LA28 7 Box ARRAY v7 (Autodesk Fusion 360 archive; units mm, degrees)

design "LA28 7 Box ARRAY" references "LA28 TOUR BLOCK", "LA28 RF1 Sheet Metal Assembly"
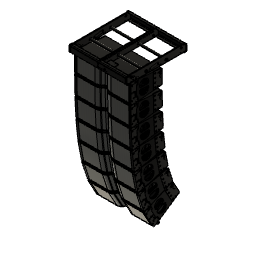
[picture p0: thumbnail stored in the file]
component_insert "Component Insert1"
as_built_joint "As-built1"
component_insert "Component Insert2"
joint "Assemble1" alignAngle 0 alignOffsetX 0 alignOffsetY 0 alignOffsetZ 5.08
component_insert "Component Insert3"
joint "Assemble2" alignAngle -1 alignOffsetX 0 alignOffsetY 0 alignOffsetZ 5.08
component_insert "Component Insert4"
component_insert "Component Insert5"
joint "Assemble3" alignAngle -2 alignOffsetX 0 alignOffsetY 0 alignOffsetZ 5.08
joint "Assemble4" alignAngle -3 alignOffsetX 0 alignOffsetY 0 alignOffsetZ 5.08
component_insert "Component Insert6"
component_insert "Component Insert7"
component_insert "Component Insert8"
joint "Assemble5" alignAngle -5 alignOffsetX 0 alignOffsetY 0 alignOffsetZ 5.08
joint "Assemble6" alignAngle -7 alignOffsetX 0 alignOffsetY 0 alignOffsetZ 5.08
joint "Assemble7" alignAngle -11 alignOffsetX 0 alignOffsetY 0 alignOffsetZ 5.08

design "la28RF1 SHEET METAL ASSEMBLY.SLDASM"
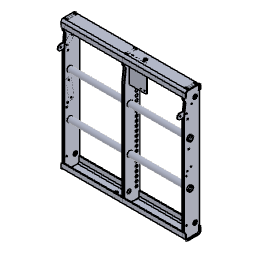
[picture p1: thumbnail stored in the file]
named bodies: "Cut-Extrude3", "Cut-Extrude2", "Mirror2", "Boss-Extrude1"

design "LA28 TOUR BLOCK" references "LA28 TOUR BLOCK.sldprt"
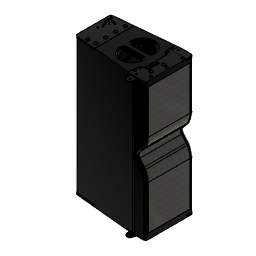
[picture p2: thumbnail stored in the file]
step "WorkingModel"
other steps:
derived_base_feature "Derived Base Feature" bodies "Fillet3"
named bodies: "Fillet3"

design "LA28 RF1 Sheet Metal Assembly" references "la28RF1 SHEET METAL ASSEMBLY.SLDASM"
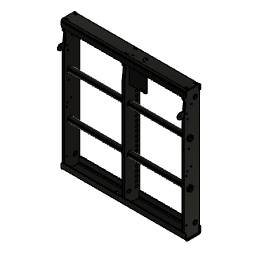
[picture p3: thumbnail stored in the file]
step "WorkingModel"
derived_instance "DerivedInstance1"
derived_instance "DerivedInstance2"
derived_instance "DerivedInstance3"
derived_instance "DerivedInstance4"
derived_instance "DerivedInstance5"
derived_instance "DerivedInstance6"
derived_instance "DerivedInstance7"
as_built_joint "As-built1"
offset_faces "OffsetFaces1" distance 0.7595 (= "0.1644 in - 0.1345 in")
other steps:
derived_base_feature "Derived Base Feature1"
derived_base_feature "Derived Base Feature1" bodies "Cut-Extrude3"
derived_base_feature "Derived Base Feature1" bodies "Cut-Extrude3"
derived_base_feature "Derived Base Feature1" bodies "Boss-Extrude1"
derived_base_feature "Derived Base Feature1" bodies "Cut-Extrude2"
derived_base_feature "Derived Base Feature1" bodies "Boss-Extrude1"
derived_base_feature "Derived Base Feature1" bodies "Cut-Extrude2"
derived_base_feature "Derived Base Feature1" bodies "Mirror2"
create_component "CreateComponent1"
create_component "CreateComponent2"
create_component "CreateComponent3"
create_component "CreateComponent4"
create_component "CreateComponent5"
create_component "CreateComponent6"
create_component "CreateComponent7"
named bodies: "Cut-Extrude3", "Cut-Extrude2", "Mirror2", "Boss-Extrude1"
